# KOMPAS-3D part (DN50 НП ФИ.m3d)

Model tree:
1. Операция без истории:1

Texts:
  DN50 НП ФИ
  133 1 134 1 135 1 136 0 50 1|SPDS|133 1 134 1 135 1 136 0 50 1
  125 1 126 1 127 1 128 0 50 1|SPDS|125 1 126 1 127 1 128 0 50 1
  129 1 130 1 131 1 132 0 50 1|SPDS|129 1 130 1 131 1 132 0 50 1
